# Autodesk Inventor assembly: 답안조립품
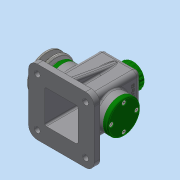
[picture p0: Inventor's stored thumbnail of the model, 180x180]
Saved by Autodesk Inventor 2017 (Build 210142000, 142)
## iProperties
Part Number: 답안조립품
Material: 일반
Document SubType Name: Assembly
Designer: MRC
Author: MRC
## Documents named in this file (14)
- C:\Users\MRC\Desktop\700907V1008\답안조립품.iam
- C:\Users\MRC\Desktop\700907V1008\본체.ipt
- C:\Users\MRC\Desktop\700907V1008\뒤커버.ipt
- C:\Users\MRC\Desktop\700907V1008\멈춤링 15 x 1.ipt
- C:\Users\MRC\Desktop\700907V1008\베어링 15 x 35 x 11.ipt
- C:\Users\MRC\Desktop\700907V1008\볼트 M4 x 10.ipt
- C:\Users\MRC\Desktop\700907V1008\볼트 M6 x 12.ipt
- C:\Users\MRC\Desktop\700907V1008\상부캡.ipt
- C:\Users\MRC\Desktop\700907V1008\앞커버.ipt
- C:\Users\MRC\Desktop\700907V1008\오일실 15 25 7.ipt
- C:\Users\MRC\Desktop\700907V1008\와셔.ipt
- C:\Users\MRC\Desktop\700907V1008\축.ipt
- C:\Users\MRC\Desktop\700907V1008\키 5 x 5 x 14.ipt
- C:\Users\MRC\Desktop\700907V1008\V-벨트풀리.ipt
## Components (1 placed, 1 different names)
1. V-벨트풀리:1
